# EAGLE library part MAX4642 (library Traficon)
High-Speed, Low-Voltage, 4?, Dual SPST CMOS Analog Switches
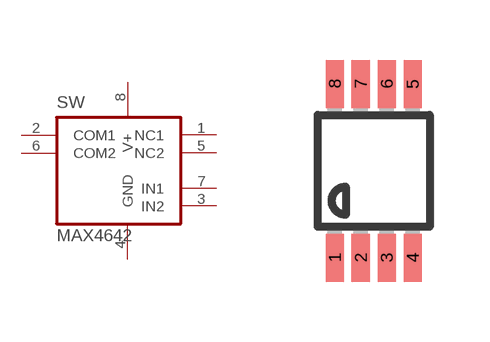
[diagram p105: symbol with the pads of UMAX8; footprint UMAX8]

Designator prefix SW

## MAX4642  [UMAX8]
1  NC1
2  COM1
3  IN2
4  GND
5  NC2
6  COM2
7  IN1
8  V+

## Footprint UMAX8 (pad centres in mm)
micro MAX Package
smd 0.45 x 1.2: 1 -0.975,-2.175; 2 -0.325,-2.175; 3 0.325,-2.175; 4 0.975,-2.175; 5 0.975,2.175; 6 0.325,2.175; 7 -0.325,2.175; 8 -0.975,2.175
